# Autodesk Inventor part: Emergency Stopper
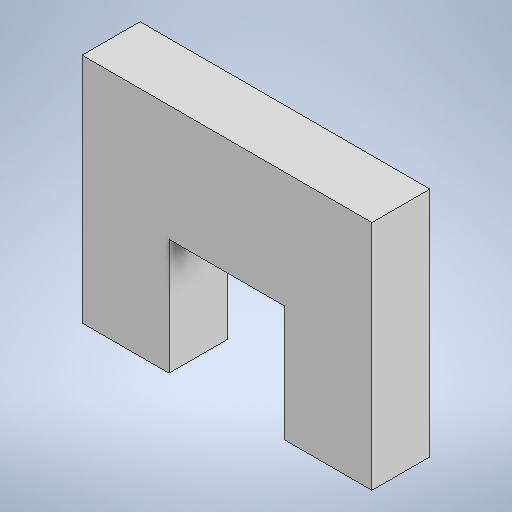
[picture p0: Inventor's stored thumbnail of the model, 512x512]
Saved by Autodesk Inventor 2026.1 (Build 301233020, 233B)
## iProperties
Created: 2026-11
Part Number: Emergency Stopper
Material: Generic
Document SubType Name: Modeling
Designer: hp
Density: 1 g/cm^3
Appearance: Default
Author: hp
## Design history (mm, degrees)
sketch "Sketch1"
  geometry: L1 (0, 0)-(50, 0); L2 (50, 0)-(50, 40); L3 (50, 40)-(0, 40); L4 (0, 40)-(0, 0); L5 (15, 20)-(35, 20); L6 (15, 20)-(15, 0); L7 (35, 20)-(35, 0); 2 further points
  constraints: 14 end point, 3 parallel, 2 horizontal, 2 midpoint, 2 perpendicular, 2 point on line, 1 vertical alignment
  dimensions: "d0" = 50 distance of L3.end L2.end; "d1" = 40 distance of L2.end L1.end; "d2" = 20 distance of L5.start L5.end; "d3" = 20 distance of L5.end L7.end
extrude "Extrusion1" new body sketch "Sketch1" distance "d4" = 10; taper "d5" = 0 deg
body "Solid1"
